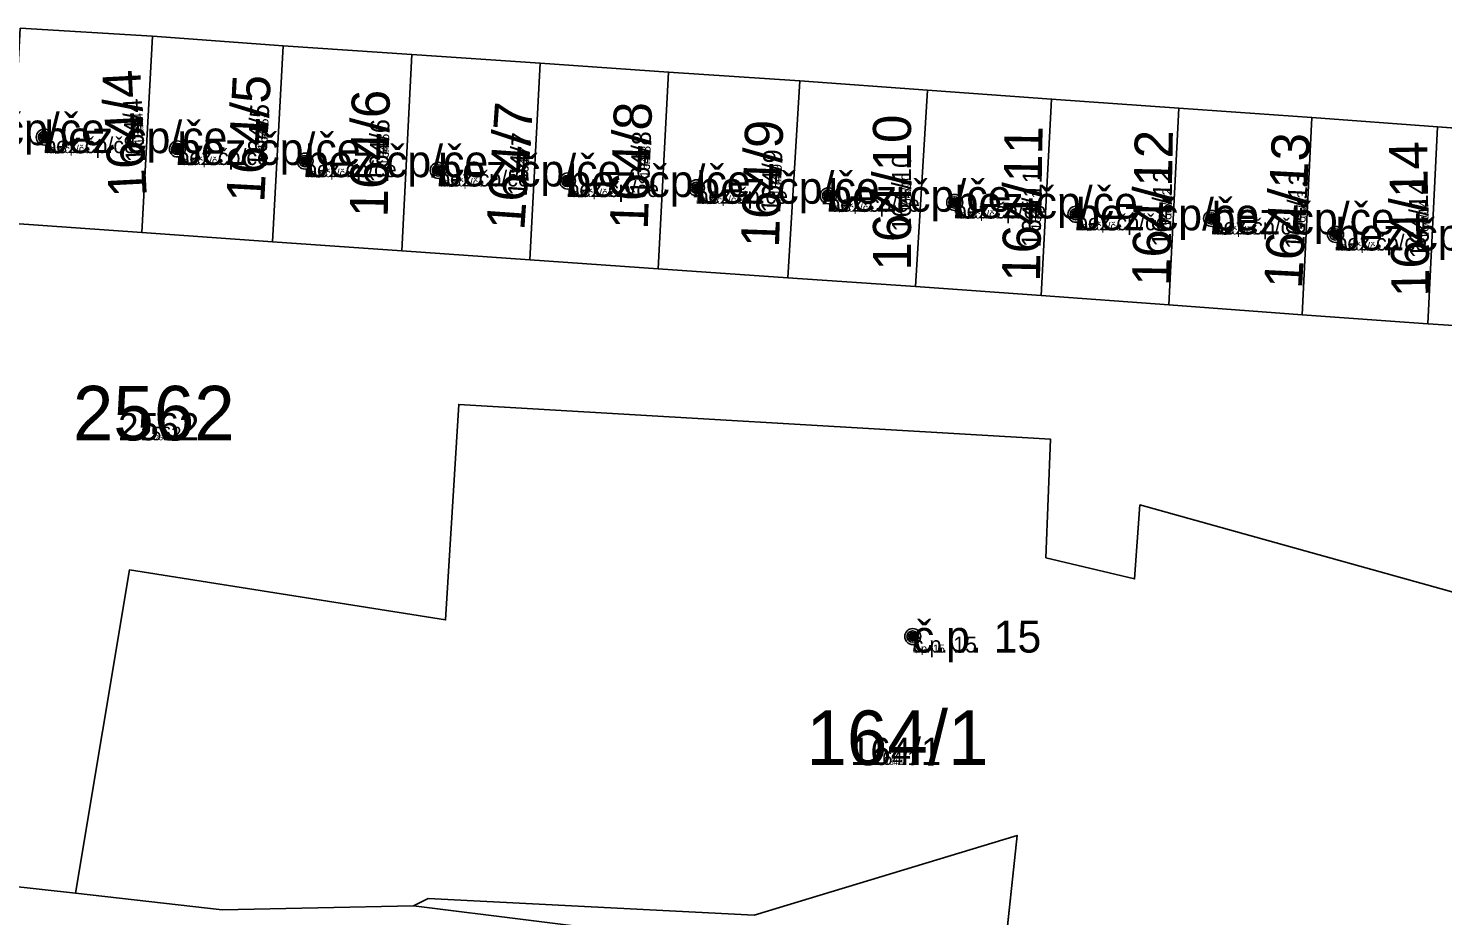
# Model space of a CAD drawing. Extents: x -744652 to -739090, y -980828 to -975855.
# Drawn here: x -742427.42 to -742383.22, y -978772.19 to -978744.47 of the extents above; entities that cross this region are included whole.
import ezdxf

# ---------------------------------------------------------------- set-up
doc = ezdxf.new("R2010")
doc.units = 0
for name, color, linetype in [('KAT_02_hranice parcel', 7, 'Continuous'), ('KAT_03_1000_st čísla parcelní', 7, 'Continuous'), ('KAT_03_1000_čísla parcelní', 7, 'Continuous'), ('KAT_03_1000_čísla popisná', 7, 'Continuous'), ('KAT_03_100_st čísla parcelní', 7, 'Continuous'), ('KAT_03_100_čísla parcelní', 7, 'Continuous'), ('KAT_03_100_čísla popisná', 7, 'Continuous'), ('KAT_03_250_st čísla parcelní', 7, 'Continuous'), ('KAT_03_250_čísla parcelní', 7, 'Continuous'), ('KAT_03_250_čísla popisná', 7, 'Continuous'), ('KAT_03_500_st čísla parcelní', 7, 'Continuous'), ('KAT_03_500_čísla parcelní', 7, 'Continuous'), ('KAT_03_500_čísla popisná', 7, 'Continuous'), ('KAT_04_vnitřní kresba', 7, 'Continuous'), ('KAT_07_1000_značky budov', 7, 'Continuous'), ('KAT_07_100_značky budov', 7, 'Continuous'), ('KAT_07_500_značky budov', 7, 'Continuous'), ('KAT_14_plocha_budovy', 7, 'Continuous')]:
    doc.layers.add(name, color=color, linetype=linetype)

msp = doc.modelspace()

# ---------------------------------------------------------------- linework, layer by layer
at = {"layer": 'KAT_02_hranice parcel'}
for p, q in [((-742423.54, -978744.72), (-742427.67, -978744.47)), ((-742423.87, -978750.85), (-742423.54, -978744.72)), ((-742419.46, -978745.02), (-742423.54, -978744.72)), ((-742419.79, -978751.14), (-742419.46, -978745.02)), ((-742415.43, -978745.29), (-742419.46, -978745.02)), ((-742415.75, -978751.42), (-742415.43, -978745.29)), ((-742411.42, -978745.56), (-742415.43, -978745.29)), ((-742411.75, -978751.7), (-742411.42, -978745.56)), ((-742407.41, -978745.84), (-742411.42, -978745.56)), ((-742407.74, -978751.98), (-742407.41, -978745.84)), ((-742403.31, -978746.11), (-742407.41, -978745.84)), ((-742403.68, -978752.26), (-742403.31, -978746.11)), ((-742399.32, -978746.4), (-742403.31, -978746.11)), ((-742399.7, -978752.54), (-742399.32, -978746.4)), ((-742395.44, -978746.68), (-742399.32, -978746.4)), ((-742395.77, -978752.82), (-742395.44, -978746.68)), ((-742391.47, -978746.97), (-742395.44, -978746.68)), ((-742391.78, -978753.11), (-742391.47, -978746.97)), ((-742387.31, -978747.26), (-742391.47, -978746.97)), ((-742387.61, -978753.42), (-742387.31, -978747.26)), ((-742383.38, -978747.55), (-742387.31, -978747.26)), ((-742383.68, -978753.7), (-742383.38, -978747.55)), ((-742379.49, -978747.84), (-742383.38, -978747.55)), ((-742428, -978750.56), (-742423.87, -978750.85)), ((-742423.87, -978750.85), (-742419.79, -978751.14)), ((-742419.79, -978751.14), (-742415.75, -978751.42)), ((-742415.75, -978751.42), (-742411.75, -978751.7)), ((-742411.75, -978751.7), (-742407.74, -978751.98)), ((-742407.74, -978751.98), (-742403.68, -978752.26)), ((-742403.68, -978752.26), (-742399.7, -978752.54)), ((-742399.7, -978752.54), (-742395.77, -978752.82)), ((-742395.77, -978752.82), (-742391.78, -978753.11)), ((-742391.78, -978753.11), (-742387.61, -978753.42)), ((-742387.61, -978753.42), (-742383.68, -978753.7)), ((-742383.68, -978753.7), (-742379.79, -978753.95))]:
    msp.add_line(p, q, dxfattribs=at)
for points in [[(-742425.94, -978771.49), (-742438.92, -978770.06), (-742441.46, -978760.66), (-742440.76, -978758.12), (-742437.78, -978749.89), (-742436.37, -978749.98)], [(-742371.69, -978765.21), (-742392.68, -978759.36), (-742392.85, -978761.67), (-742395.62, -978761.01), (-742395.48, -978757.3), (-742413.97, -978756.22), (-742414.38, -978762.95), (-742424.26, -978761.39), (-742425.94, -978771.49)], [(-742425.94, -978771.49), (-742421.36, -978772.01), (-742415.38, -978771.88), (-742397, -978774.17), (-742373.14, -978780.68)]]:
    msp.add_lwpolyline(points, dxfattribs=at)
at = {"layer": 'KAT_03_1000_čísla popisná'}
for centre in [(-742426.92, -978747.87), (-742426.92, -978747.87), (-742422.76, -978748.24), (-742422.76, -978748.24), (-742418.77, -978748.62), (-742418.77, -978748.62), (-742414.61, -978748.91), (-742414.61, -978748.91), (-742410.57, -978749.24), (-742410.57, -978749.24), (-742406.54, -978749.45), (-742406.54, -978749.45), (-742402.42, -978749.7), (-742402.42, -978749.7), (-742398.47, -978749.91), (-742398.47, -978749.91), (-742394.68, -978750.28), (-742394.68, -978750.28), (-742390.44, -978750.41), (-742390.44, -978750.41), (-742386.57, -978750.91), (-742386.57, -978750.91), (-742399.78, -978763.47), (-742399.78, -978763.47)]:
    msp.add_circle(centre, 0.25, dxfattribs=at)
at = {"layer": 'KAT_03_100_čísla popisná'}
for centre in [(-742426.92, -978747.87), (-742426.92, -978747.87), (-742422.76, -978748.24), (-742422.76, -978748.24), (-742418.77, -978748.62), (-742418.77, -978748.62), (-742414.61, -978748.91), (-742414.61, -978748.91), (-742410.57, -978749.24), (-742410.57, -978749.24), (-742406.54, -978749.45), (-742406.54, -978749.45), (-742402.42, -978749.7), (-742402.42, -978749.7), (-742398.47, -978749.91), (-742398.47, -978749.91), (-742394.68, -978750.28), (-742394.68, -978750.28), (-742390.44, -978750.41), (-742390.44, -978750.41), (-742386.57, -978750.91), (-742386.57, -978750.91), (-742399.78, -978763.47), (-742399.78, -978763.47)]:
    msp.add_circle(centre, 0.025, dxfattribs=at)
at = {"layer": 'KAT_03_250_čísla popisná'}
for centre in [(-742426.92, -978747.87), (-742426.92, -978747.87), (-742422.76, -978748.24), (-742422.76, -978748.24), (-742418.77, -978748.62), (-742418.77, -978748.62), (-742414.61, -978748.91), (-742414.61, -978748.91), (-742410.57, -978749.24), (-742410.57, -978749.24), (-742406.54, -978749.45), (-742406.54, -978749.45), (-742402.42, -978749.7), (-742402.42, -978749.7), (-742398.47, -978749.91), (-742398.47, -978749.91), (-742394.68, -978750.28), (-742394.68, -978750.28), (-742390.44, -978750.41), (-742390.44, -978750.41), (-742386.57, -978750.91), (-742386.57, -978750.91), (-742399.78, -978763.47), (-742399.78, -978763.47)]:
    msp.add_circle(centre, 0.0625, dxfattribs=at)
at = {"layer": 'KAT_03_500_čísla popisná'}
for centre in [(-742426.92, -978747.87), (-742426.92, -978747.87), (-742422.76, -978748.24), (-742422.76, -978748.24), (-742418.77, -978748.62), (-742418.77, -978748.62), (-742414.61, -978748.91), (-742414.61, -978748.91), (-742410.57, -978749.24), (-742410.57, -978749.24), (-742406.54, -978749.45), (-742406.54, -978749.45), (-742402.42, -978749.7), (-742402.42, -978749.7), (-742398.47, -978749.91), (-742398.47, -978749.91), (-742394.68, -978750.28), (-742394.68, -978750.28), (-742390.44, -978750.41), (-742390.44, -978750.41), (-742386.57, -978750.91), (-742386.57, -978750.91), (-742399.78, -978763.47), (-742399.78, -978763.47)]:
    msp.add_circle(centre, 0.125, dxfattribs=at)
at = {"layer": 'KAT_04_vnitřní kresba'}
for p, q in [((-742396.52, -978769.68), (-742404.74, -978772.17)), ((-742396.52, -978769.68), (-742397, -978774.17)), ((-742414.92, -978771.65), (-742415.38, -978771.88)), ((-742404.74, -978772.17), (-742414.92, -978771.65))]:
    msp.add_line(p, q, dxfattribs=at)
at = {"layer": 'KAT_07_1000_značky budov'}
for centre in [(-742426.927, -978747.869), (-742422.767, -978748.239), (-742418.777, -978748.619), (-742414.617, -978748.909), (-742410.577, -978749.239), (-742406.547, -978749.449), (-742402.427, -978749.699), (-742398.477, -978749.909), (-742394.687, -978750.279), (-742390.447, -978750.409), (-742386.577, -978750.909), (-742399.787, -978763.469)]:
    msp.add_circle(centre, 0.175, dxfattribs=at)
at = {"layer": 'KAT_07_100_značky budov'}
for centre in [(-742426.921, -978747.87), (-742422.761, -978748.24), (-742418.771, -978748.62), (-742414.611, -978748.91), (-742410.571, -978749.24), (-742406.541, -978749.45), (-742402.421, -978749.7), (-742398.471, -978749.91), (-742394.681, -978750.28), (-742390.441, -978750.41), (-742386.571, -978750.91), (-742399.781, -978763.47)]:
    msp.add_circle(centre, 0.0175, dxfattribs=at)
at = {"layer": 'KAT_07_500_značky budov'}
for centre, radius in [((-742426.923, -978747.87), 0.0875), ((-742426.922, -978747.87), 0.0438), ((-742422.763, -978748.24), 0.0875), ((-742422.762, -978748.24), 0.0438), ((-742418.773, -978748.62), 0.0875), ((-742418.772, -978748.62), 0.0438), ((-742414.613, -978748.91), 0.0875), ((-742414.612, -978748.91), 0.0438), ((-742410.573, -978749.24), 0.0875), ((-742410.572, -978749.24), 0.0438), ((-742406.543, -978749.45), 0.0875), ((-742406.542, -978749.45), 0.0438), ((-742402.423, -978749.7), 0.0875), ((-742402.422, -978749.7), 0.0438), ((-742398.473, -978749.91), 0.0875), ((-742398.472, -978749.91), 0.0438), ((-742394.683, -978750.28), 0.0875), ((-742394.682, -978750.28), 0.0438), ((-742390.443, -978750.41), 0.0875), ((-742390.442, -978750.41), 0.0438), ((-742386.573, -978750.91), 0.0875), ((-742386.572, -978750.91), 0.0438), ((-742399.783, -978763.47), 0.0875), ((-742399.782, -978763.47), 0.0438)]:
    msp.add_circle(centre, radius, dxfattribs=at)
at = {"layer": 'KAT_14_plocha_budovy'}
for points in [[(-742423.87, -978750.85), (-742423.54, -978744.72), (-742427.67, -978744.47), (-742428, -978750.56)], [(-742423.87, -978750.85), (-742419.79, -978751.14), (-742419.46, -978745.02), (-742423.54, -978744.72)], [(-742419.79, -978751.14), (-742415.75, -978751.42), (-742415.43, -978745.29), (-742419.46, -978745.02)], [(-742415.75, -978751.42), (-742411.75, -978751.7), (-742411.42, -978745.56), (-742415.43, -978745.29)], [(-742411.75, -978751.7), (-742407.74, -978751.98), (-742407.41, -978745.84), (-742411.42, -978745.56)], [(-742407.74, -978751.98), (-742403.68, -978752.26), (-742403.31, -978746.11), (-742407.41, -978745.84)], [(-742403.68, -978752.26), (-742399.7, -978752.54), (-742399.32, -978746.4), (-742403.31, -978746.11)], [(-742399.7, -978752.54), (-742395.77, -978752.82), (-742395.44, -978746.68), (-742399.32, -978746.4)], [(-742395.77, -978752.82), (-742391.78, -978753.11), (-742391.47, -978746.97), (-742395.44, -978746.68)], [(-742391.78, -978753.11), (-742387.61, -978753.42), (-742387.31, -978747.26), (-742391.47, -978746.97)], [(-742387.61, -978753.42), (-742383.68, -978753.7), (-742383.38, -978747.55), (-742387.31, -978747.26)], [(-742383.68, -978753.7), (-742379.79, -978753.95), (-742379.49, -978747.84), (-742383.38, -978747.55)], [(-742397, -978774.17), (-742373.14, -978780.68), (-742371.69, -978765.21), (-742392.68, -978759.36), (-742392.85, -978761.67), (-742395.62, -978761.01), (-742395.48, -978757.3), (-742413.97, -978756.22), (-742414.38, -978762.95), (-742424.26, -978761.39), (-742425.94, -978771.49), (-742421.36, -978772.01), (-742415.38, -978771.88), (-742414.92, -978771.65), (-742404.74, -978772.17), (-742396.52, -978769.68)]]:
    msp.add_lwpolyline(points, close=True, dxfattribs=at)

# ---------------------------------------------------------------- texts
at = {"layer": 'KAT_03_1000_st čísla parcelní'}
for s, rotation, p in [('164/4', 93, (-742423.714, -978749.717)), ('164/5', 87, (-742420.047, -978749.929)), ('164/6', 89, (-742416.188, -978750.381)), ('164/7', 86, (-742411.921, -978750.798)), ('164/8', 88, (-742408.063, -978750.77)), ('164/9', 88, (-742403.963, -978751.33)), ('164/10', 90, (-742399.835, -978752.034)), ('164/11', 89, (-742395.805, -978752.394)), ('164/12', 89, (-742391.735, -978752.524)), ('164/13', 87, (-742387.616, -978752.621)), ('164/14', 91, (-742383.624, -978752.853))]:
    msp.add_text(s, height=1.19, rotation=rotation, dxfattribs=at).set_placement(p)
msp.add_text('164/1', height=1.7, dxfattribs=at).set_placement((-742403.103, -978767.48))
at = {"layer": 'KAT_03_1000_čísla parcelní'}
msp.add_text('2562', height=1.7, dxfattribs=at).set_placement((-742426.027, -978757.34))
at = {"layer": 'KAT_03_1000_čísla popisná'}
for s, height, p in [('bez čp/če', 1, (-742430.75, -978748.12)), ('bez čp/če', 1, (-742426.92, -978748.37)), ('bez čp/če', 1, (-742422.76, -978748.74)), ('bez čp/če', 1, (-742418.77, -978749.12)), ('bez čp/če', 1, (-742414.61, -978749.41)), ('bez čp/če', 1, (-742410.57, -978749.74)), ('bez čp/če', 1, (-742406.54, -978749.95)), ('bez čp/če', 1, (-742402.42, -978750.2)), ('bez čp/če', 1, (-742398.47, -978750.41)), ('bez čp/če', 1, (-742394.68, -978750.78)), ('bez čp/če', 1, (-742390.44, -978750.91)), ('bez čp/če', 1, (-742386.57, -978751.41)), ('č.p. 15', 1, (-742399.78, -978763.97)), ('164/1', 0.017, (-742400.393, -978767.48))]:
    msp.add_text(s, height=height, dxfattribs=at).set_placement(p)
for s, rotation, p in [('164/4', 93, (-742423.826, -978747.582)), ('164/5', 87, (-742419.933, -978747.762)), ('164/6', 89, (-742416.151, -978748.243)), ('164/7', 86, (-742411.774, -978748.693)), ('164/8', 88, (-742407.988, -978748.619)), ('164/9', 88, (-742403.888, -978749.193)), ('164/10', 90, (-742399.835, -978749.641)), ('164/12', 89, (-742391.693, -978750.099)), ('164/11', 89, (-742395.768, -978750.261)), ('164/13', 87, (-742387.489, -978750.19)), ('164/14', 91, (-742383.665, -978750.479))]:
    msp.add_text(s, height=0.0119, rotation=rotation, dxfattribs=at).set_placement(p)
at = {"layer": 'KAT_03_100_st čísla parcelní'}
for s, rotation, p in [('164/4', 93, (-742423.816, -978747.776)), ('164/5', 87, (-742419.944, -978747.959)), ('164/6', 89, (-742416.154, -978748.438)), ('164/7', 86, (-742411.787, -978748.884)), ('164/8', 88, (-742407.995, -978748.815)), ('164/9', 88, (-742403.895, -978749.388)), ('164/10', 90, (-742399.835, -978749.859)), ('164/11', 89, (-742395.771, -978750.455)), ('164/12', 89, (-742391.697, -978750.319)), ('164/13', 87, (-742387.5, -978750.411)), ('164/14', 91, (-742383.662, -978750.695))]:
    msp.add_text(s, height=0.119, rotation=rotation, dxfattribs=at).set_placement(p)
msp.add_text('164/1', height=0.17, dxfattribs=at).set_placement((-742400.64, -978767.48))
at = {"layer": 'KAT_03_100_čísla parcelní'}
msp.add_text('2562', height=0.17, dxfattribs=at).set_placement((-742423.473, -978757.34))
at = {"layer": 'KAT_03_100_čísla popisná'}
for s, rotation, p in [('164/4', 93, (-742423.827, -978747.563)), ('164/5', 87, (-742419.932, -978747.742)), ('164/6', 89, (-742416.15, -978748.224)), ('164/7', 86, (-742411.772, -978748.674)), ('164/8', 88, (-742407.987, -978748.6)), ('164/9', 88, (-742403.888, -978749.174)), ('164/10', 90, (-742399.835, -978749.619)), ('164/11', 89, (-742395.767, -978750.242)), ('164/12', 89, (-742391.692, -978750.077)), ('164/13', 87, (-742387.487, -978750.167)), ('164/14', 91, (-742383.666, -978750.457))]:
    msp.add_text(s, height=0.00119, rotation=rotation, dxfattribs=at).set_placement(p)
for s, height, p in [('bez čp/če', 0.1, (-742426.92, -978748.37)), ('bez čp/če', 0.1, (-742422.76, -978748.74)), ('bez čp/če', 0.1, (-742418.77, -978749.12)), ('bez čp/če', 0.1, (-742414.61, -978749.41)), ('bez čp/če', 0.1, (-742410.57, -978749.74)), ('bez čp/če', 0.1, (-742406.54, -978749.95)), ('bez čp/če', 0.1, (-742402.42, -978750.2)), ('bez čp/če', 0.1, (-742398.47, -978750.41)), ('bez čp/če', 0.1, (-742394.68, -978750.78)), ('bez čp/če', 0.1, (-742390.44, -978750.91)), ('bez čp/če', 0.1, (-742386.57, -978751.41)), ('č.p. 15', 0.1, (-742399.78, -978763.97)), ('164/1', 0.0017, (-742400.369, -978767.48))]:
    msp.add_text(s, height=height, dxfattribs=at).set_placement(p)
at = {"layer": 'KAT_03_250_st čísla parcelní'}
for s, rotation, p in [('164/4', 93, (-742423.799, -978748.1)), ('164/5', 87, (-742419.961, -978748.287)), ('164/6', 89, (-742416.16, -978748.762)), ('164/7', 86, (-742411.809, -978749.203)), ('164/8', 88, (-742408.006, -978749.141)), ('164/9', 88, (-742403.906, -978749.711)), ('164/10', 90, (-742399.835, -978750.221)), ('164/11', 89, (-742395.777, -978750.778)), ('164/12', 89, (-742391.703, -978750.687)), ('164/13', 87, (-742387.519, -978750.779)), ('164/14', 91, (-742383.655, -978751.054))]:
    msp.add_text(s, height=0.2975, rotation=rotation, dxfattribs=at).set_placement(p)
msp.add_text('164/1', height=0.425, dxfattribs=at).set_placement((-742401.05, -978767.48))
at = {"layer": 'KAT_03_250_čísla parcelní'}
msp.add_text('2562', height=0.425, dxfattribs=at).set_placement((-742423.899, -978757.34))
at = {"layer": 'KAT_03_250_čísla popisná'}
for s, rotation, p in [('164/4', 93, (-742423.827, -978747.566)), ('164/5', 87, (-742419.933, -978747.745)), ('164/6', 89, (-742416.15, -978748.227)), ('164/7', 86, (-742411.773, -978748.677)), ('164/8', 88, (-742407.987, -978748.603)), ('164/9', 88, (-742403.888, -978749.177)), ('164/10', 90, (-742399.835, -978749.623)), ('164/11', 89, (-742395.767, -978750.245)), ('164/12', 89, (-742391.692, -978750.08)), ('164/13', 87, (-742387.488, -978750.171)), ('164/14', 91, (-742383.666, -978750.461))]:
    msp.add_text(s, height=0.00297, rotation=rotation, dxfattribs=at).set_placement(p)
for s, height, p in [('bez čp/če', 0.25, (-742426.92, -978748.37)), ('bez čp/če', 0.25, (-742422.76, -978748.74)), ('bez čp/če', 0.25, (-742418.77, -978749.12)), ('bez čp/če', 0.25, (-742414.61, -978749.41)), ('bez čp/če', 0.25, (-742410.57, -978749.74)), ('bez čp/če', 0.25, (-742406.54, -978749.95)), ('bez čp/če', 0.25, (-742402.42, -978750.2)), ('bez čp/če', 0.25, (-742398.47, -978750.41)), ('bez čp/če', 0.25, (-742394.68, -978750.78)), ('bez čp/če', 0.25, (-742390.44, -978750.91)), ('bez čp/če', 0.25, (-742386.57, -978751.41)), ('č.p. 15', 0.25, (-742399.78, -978763.97)), ('164/1', 0.00425, (-742400.373, -978767.48))]:
    msp.add_text(s, height=height, dxfattribs=at).set_placement(p)
at = {"layer": 'KAT_03_500_st čísla parcelní'}
for s, rotation, p in [('164/4', 93, (-742423.771, -978748.639)), ('164/5', 87, (-742419.99, -978748.834)), ('164/6', 89, (-742416.169, -978749.301)), ('164/7', 86, (-742411.847, -978749.735)), ('164/8', 88, (-742408.025, -978749.684)), ('164/9', 88, (-742403.925, -978750.251)), ('164/10', 90, (-742399.835, -978750.825)), ('164/11', 89, (-742395.786, -978751.317)), ('164/12', 89, (-742391.714, -978751.299)), ('164/13', 87, (-742387.552, -978751.393)), ('164/14', 91, (-742383.645, -978751.654))]:
    msp.add_text(s, height=0.595, rotation=rotation, dxfattribs=at).set_placement(p)
msp.add_text('164/1', height=0.85, dxfattribs=at).set_placement((-742401.734, -978767.48))
at = {"layer": 'KAT_03_500_čísla parcelní'}
msp.add_text('2562', height=0.85, dxfattribs=at).set_placement((-742424.608, -978757.34))
at = {"layer": 'KAT_03_500_čísla popisná'}
for s, height, p in [('bez čp/če', 0.5, (-742426.92, -978748.37)), ('bez čp/če', 0.5, (-742422.76, -978748.74)), ('bez čp/če', 0.5, (-742418.77, -978749.12)), ('bez čp/če', 0.5, (-742414.61, -978749.41)), ('bez čp/če', 0.5, (-742410.57, -978749.74)), ('bez čp/če', 0.5, (-742406.54, -978749.95)), ('bez čp/če', 0.5, (-742402.42, -978750.2)), ('bez čp/če', 0.5, (-742398.47, -978750.41)), ('bez čp/če', 0.5, (-742394.68, -978750.78)), ('bez čp/če', 0.5, (-742390.44, -978750.91)), ('bez čp/če', 0.5, (-742386.57, -978751.41)), ('č.p. 15', 0.5, (-742399.78, -978763.97)), ('164/1', 0.0085, (-742400.38, -978767.48))]:
    msp.add_text(s, height=height, dxfattribs=at).set_placement(p)
for s, rotation, p in [('164/4', 93, (-742423.826, -978747.571)), ('164/5', 87, (-742419.933, -978747.751)), ('164/6', 89, (-742416.15, -978748.233)), ('164/7', 86, (-742411.773, -978748.682)), ('164/8', 88, (-742407.988, -978748.609)), ('164/9', 88, (-742403.888, -978749.183)), ('164/10', 90, (-742399.835, -978749.629)), ('164/12', 89, (-742391.692, -978750.087)), ('164/11', 89, (-742395.768, -978750.25)), ('164/13', 87, (-742387.488, -978750.177)), ('164/14', 91, (-742383.666, -978750.467))]:
    msp.add_text(s, height=0.00595, rotation=rotation, dxfattribs=at).set_placement(p)

doc.saveas('drawing.dxf')
